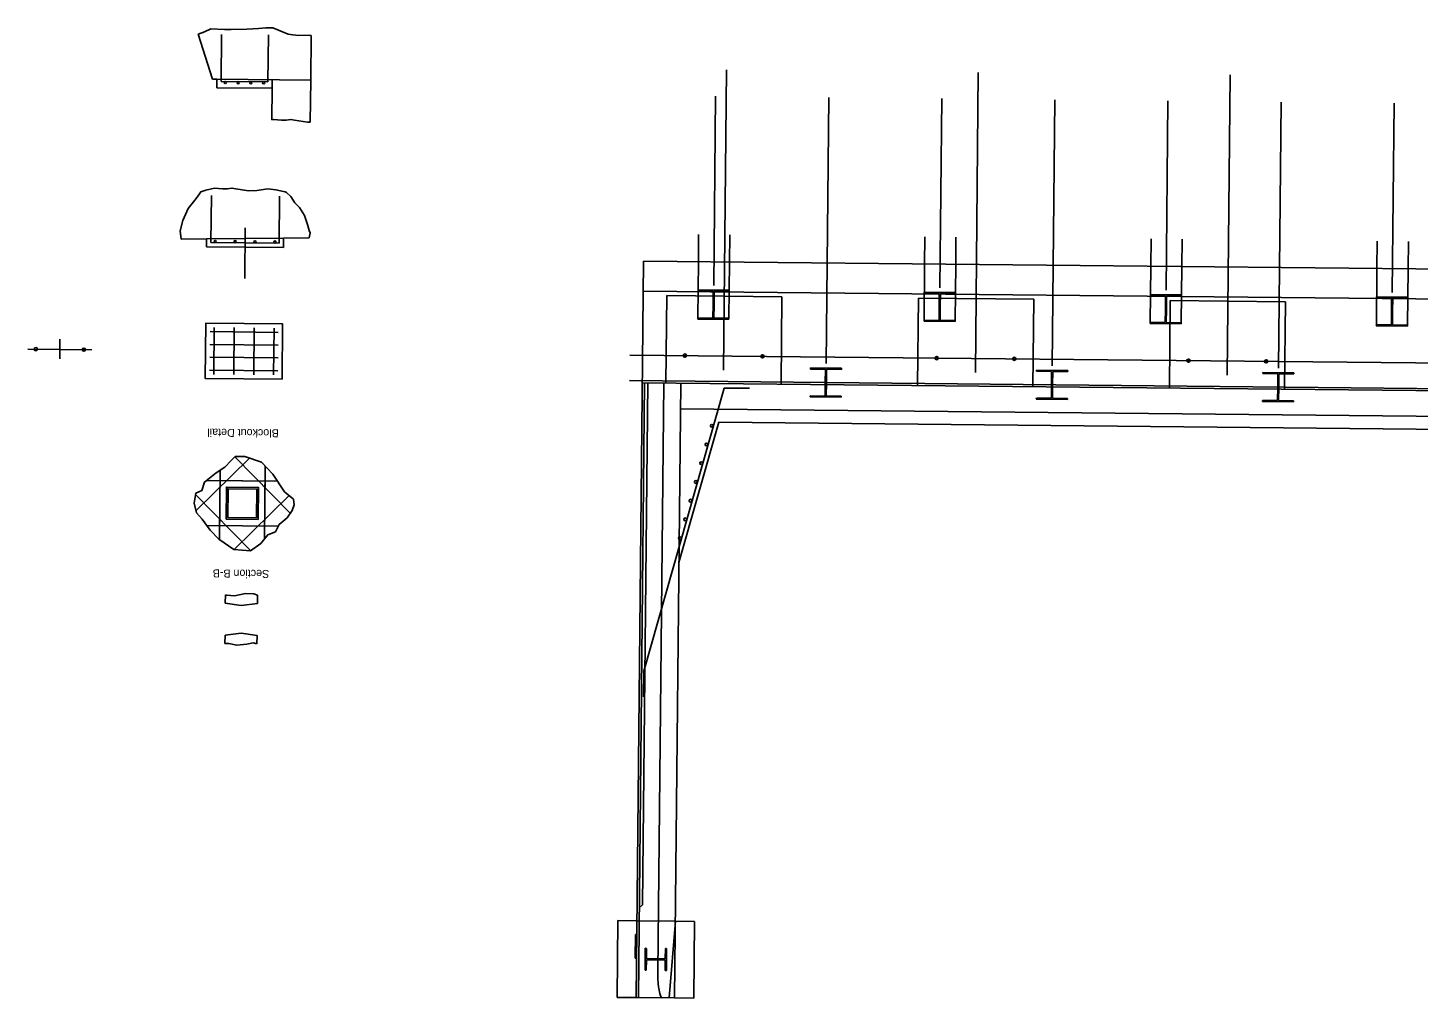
# Model space of a CAD drawing. Extents: x 632022 to 632319, y 373181 to 373252.
# Drawn here: x 632208.9 to 632263.2, y 373182 to 373219.8 of the extents above; entities that cross this region are included whole.
import ezdxf

# ---------------------------------------------------------------- set-up
doc = ezdxf.new("R2010")
doc.units = 0
for name, color, linetype in [('B_Boring', 7, 'Continuous'), ('B_Boring Annot', 7, 'Continuous'), ('BD-LEGEND', 7, 'Continuous'), ('BD-PROP-COSS', 7, 'Continuous'), ('BD-REMOVE', 7, 'Continuous'), ('R_Anno_Text', 7, 'Continuous'), ('R_Border_Scale', 7, 'Continuous'), ('R_Proposed Const Limits Cut', 7, 'Continuous'), ('R_Proposed Const Limits Fill', 7, 'Continuous'), ('R_Road Edge of Travel', 7, 'Continuous'), ('R_Shade Removal', 7, 'Continuous'), ('R_Wall', 7, 'Continuous')]:
    doc.layers.add(name, color=color, linetype=linetype)

msp = doc.modelspace()

# ---------------------------------------------------------------- linework, layer by layer
at = {"layer": 'B_Boring'}
for p, q in [((632233.142, 373205.975), (632232.94, 373185.601)), ((632232.814, 373185.477), (632232.94, 373185.601)), ((632234.225, 373184.963), (632232.725, 373184.978))]:
    msp.add_line(p, q, dxfattribs=at)
at = {"layer": 'B_Boring Annot'}
for p, q in [((632208.934, 373207.299), (632211.434, 373207.274)), ((632232.445, 373207.065), (632318.441, 373206.21))]:
    msp.add_line(p, q, dxfattribs=at)
at = {"layer": 'BD-LEGEND'}
for p, q in [((632216.148, 373217.835), (632215.582, 373219.591)), ((632219.999, 373219.547), (632219.981, 373217.797)), ((632216.148, 373217.835), (632216.315, 373217.834)), ((632219.981, 373217.797), (632219.965, 373216.163)), ((632218.466, 373216.251), (632218.478, 373217.479))]:
    msp.add_line(p, q, dxfattribs=at)
at = {"layer": 'BD-PROP-COSS'}
for p, q in [((632216.48, 373217.749), (632216.499, 373219.582)), ((632218.314, 373217.731), (632218.332, 373219.564)), ((632216.48, 373217.749), (632218.314, 373217.731)), ((632216.085, 373211.46), (632216.103, 373213.294)), ((632218.751, 373211.434), (632218.769, 373213.267)), ((632218.751, 373211.434), (632216.085, 373211.46)), ((632216.05, 373207.978), (632218.717, 373207.951)), ((632216.2, 373206.31), (632216.218, 373208.143)), ((632216.978, 373206.302), (632216.996, 373208.135)), ((632217.774, 373208.128), (632217.756, 373206.294)), ((632218.552, 373208.12), (632218.533, 373206.287)), ((632218.712, 373207.451), (632216.045, 373207.478)), ((632218.707, 373206.951), (632216.04, 373206.978)), ((632218.702, 373206.452), (632216.035, 373206.478)), ((632232.99, 373194.726), (632236.123, 373205.778)), ((632236.123, 373205.778), (632237.123, 373205.768)), ((632217.021, 373203.091), (632219.181, 373200.887)), ((632215.503, 373200.991), (632217.592, 373203.039)), ((632216.45, 373202.572), (632216.423, 373199.855)), ((632218.201, 373202.737), (632218.173, 373199.883)), ((632215.904, 373202.165), (632218.687, 373202.138)), ((632218.57, 373202.139), (632216.07, 373202.164)), ((632216.424, 373200.035), (632216.449, 373202.535)), ((632218.174, 373200.018), (632218.199, 373202.518)), ((632215.489, 373201.618), (632217.633, 373199.431)), ((632216.99, 373199.473), (632219.138, 373201.579)), ((632218.72, 373200.387), (632215.916, 373200.415)), ((632232.99, 373194.726), (632232.98, 373193.726))]:
    msp.add_line(p, q, dxfattribs=at)
for centre, radius in [((632216.647, 373217.705), 0.0417), ((632217.147, 373217.7), 0.0417), ((632217.647, 373217.695), 0.0417), ((632218.147, 373217.691), 0.0417), ((632216.252, 373211.5), 0.0417), ((632217.029, 373211.493), 0.0417), ((632217.807, 373211.485), 0.0417), ((632218.585, 373211.477), 0.0417), ((632235.646, 373204.304), 0.0556), ((632235.439, 373203.573), 0.0556), ((632235.232, 373202.842), 0.0556), ((632235.025, 373202.111), 0.0556), ((632234.818, 373201.379), 0.0556), ((632234.611, 373200.648), 0.0556), ((632234.404, 373199.917), 0.0556)]:
    msp.add_circle(centre, radius, dxfattribs=at)
at = {"layer": 'R_Anno_Text'}
for centre in [(632209.246, 373207.296), (632211.121, 373207.277), (632234.596, 373207.044), (632237.627, 373207.013), (632244.429, 373206.946), (632247.46, 373206.916), (632254.262, 373206.848), (632257.293, 373206.818)]:
    msp.add_circle(centre, 0.0625, dxfattribs=at)
at = {"layer": 'R_Border_Scale'}
for p, q in [((632219.981, 373217.797), (632216.315, 373217.834)), ((632218.478, 373217.479), (632218.481, 373217.812)), ((632218.92, 373211.629), (632215.919, 373211.599))]:
    msp.add_line(p, q, dxfattribs=at)
at = {"layer": 'R_Proposed Const Limits Cut'}
msp.add_lwpolyline([(632232.711, 373183.519), (632232.659, 373183.52), (632232.668, 373184.437), (632232.72, 373184.436)], close=True, dxfattribs=at)
at = {"layer": 'R_Proposed Const Limits Fill'}
for p, q in [((632236.222, 373218.196), (632236.106, 373206.479)), ((632246.055, 373218.098), (632245.939, 373206.381)), ((632255.888, 373218), (632255.772, 373206.283)), ((632217.424, 373212.034), (632217.404, 373210.054)), ((632210.188, 373207.69), (632210.18, 373206.912))]:
    msp.add_line(p, q, dxfattribs=at)
at = {"layer": 'R_Road Edge of Travel'}
for p, q in [((632235.123, 373210.705), (632235.133, 373211.773)), ((632236.339, 373210.693), (632236.35, 373211.761)), ((632243.956, 373210.617), (632243.966, 373211.685)), ((632245.172, 373210.605), (632245.183, 373211.673)), ((632252.789, 373210.53), (632252.799, 373211.597)), ((632254.005, 373210.517), (632254.016, 373211.585)), ((632261.622, 373210.442), (632261.632, 373211.51)), ((632262.838, 373210.43), (632262.849, 373211.498)), ((632235.101, 373208.514), (632235.123, 373210.705)), ((632236.318, 373208.502), (632236.339, 373210.693)), ((632243.934, 373208.426), (632243.956, 373210.617)), ((632245.151, 373208.414), (632245.172, 373210.605)), ((632252.767, 373208.338), (632252.789, 373210.53)), ((632253.983, 373208.326), (632254.005, 373210.517)), ((632261.6, 373208.251), (632261.622, 373210.442)), ((632262.816, 373208.238), (632262.838, 373210.43)), ((632235.112, 373209.605), (632236.329, 373209.593)), ((632235.112, 373209.563), (632235.112, 373209.605)), ((632235.112, 373209.605), (632236.329, 373209.593)), ((632235.112, 373209.563), (632235.112, 373209.605)), ((632235.112, 373209.563), (632235.699, 373209.557)), ((632235.112, 373209.563), (632235.699, 373209.557)), ((632235.699, 373209.557), (632235.694, 373209.033)), ((632235.699, 373209.557), (632235.694, 373209.033)), ((632235.741, 373209.557), (632235.736, 373209.032)), ((632235.741, 373209.557), (632235.736, 373209.032)), ((632236.328, 373209.551), (632235.741, 373209.557)), ((632236.328, 373209.551), (632235.741, 373209.557)), ((632236.328, 373209.551), (632236.329, 373209.593)), ((632236.328, 373209.551), (632236.329, 373209.593)), ((632243.944, 373209.475), (632243.945, 373209.517)), ((632243.944, 373209.475), (632244.532, 373209.469)), ((632243.945, 373209.517), (632245.161, 373209.505)), ((632244.532, 373209.469), (632244.526, 373208.945)), ((632244.574, 373209.469), (632244.569, 373208.944)), ((632245.161, 373209.463), (632244.574, 373209.469)), ((632245.161, 373209.463), (632245.161, 373209.505)), ((632252.777, 373209.387), (632252.778, 373209.43)), ((632252.777, 373209.387), (632253.365, 373209.382)), ((632252.778, 373209.43), (632253.994, 373209.417)), ((632253.365, 373209.382), (632253.359, 373208.857)), ((632253.407, 373209.381), (632253.401, 373208.857)), ((632253.994, 373209.375), (632253.407, 373209.381)), ((632253.994, 373209.375), (632253.994, 373209.417)), ((632261.61, 373209.3), (632261.611, 373209.342)), ((632261.61, 373209.3), (632262.197, 373209.294)), ((632261.611, 373209.342), (632262.827, 373209.33)), ((632262.197, 373209.294), (632262.192, 373208.769)), ((632262.24, 373209.293), (632262.234, 373208.769)), ((632262.827, 373209.288), (632262.24, 373209.293)), ((632262.827, 373209.288), (632262.827, 373209.33)), ((632235.101, 373208.514), (632235.101, 373208.472)), ((632235.101, 373208.514), (632235.688, 373208.508)), ((632235.101, 373208.514), (632235.101, 373208.472)), ((632235.101, 373208.514), (632235.688, 373208.508)), ((632235.688, 373208.508), (632235.694, 373209.033)), ((632235.688, 373208.508), (632235.694, 373209.033)), ((632235.736, 373209.032), (632235.694, 373209.033)), ((632235.736, 373209.032), (632235.694, 373209.033)), ((632235.73, 373208.508), (632235.736, 373209.032)), ((632235.73, 373208.508), (632235.736, 373209.032)), ((632244.521, 373208.42), (632244.526, 373208.945)), ((632244.569, 373208.944), (632244.526, 373208.945)), ((632244.563, 373208.42), (632244.569, 373208.944)), ((632253.354, 373208.333), (632253.359, 373208.857)), ((632253.401, 373208.857), (632253.359, 373208.857)), ((632253.396, 373208.332), (632253.401, 373208.857)), ((632262.187, 373208.245), (632262.192, 373208.769)), ((632262.234, 373208.769), (632262.192, 373208.769)), ((632262.229, 373208.244), (632262.234, 373208.769)), ((632235.101, 373208.472), (632236.317, 373208.46)), ((632235.101, 373208.472), (632236.317, 373208.46)), ((632236.318, 373208.502), (632235.73, 373208.508)), ((632236.318, 373208.502), (632235.73, 373208.508)), ((632236.318, 373208.502), (632236.317, 373208.46)), ((632236.318, 373208.502), (632236.317, 373208.46)), ((632243.934, 373208.426), (632243.934, 373208.384)), ((632243.934, 373208.426), (632244.521, 373208.42)), ((632243.934, 373208.384), (632245.15, 373208.372)), ((632245.151, 373208.414), (632244.563, 373208.42)), ((632245.151, 373208.414), (632245.15, 373208.372)), ((632252.767, 373208.338), (632252.766, 373208.296)), ((632252.766, 373208.296), (632253.983, 373208.284)), ((632252.767, 373208.338), (632253.354, 373208.333)), ((632253.983, 373208.326), (632253.396, 373208.332)), ((632253.983, 373208.326), (632253.983, 373208.284)), ((632261.6, 373208.251), (632261.599, 373208.208)), ((632261.599, 373208.208), (632262.816, 373208.196)), ((632261.6, 373208.251), (632262.187, 373208.245)), ((632262.816, 373208.238), (632262.229, 373208.244)), ((632262.816, 373208.238), (632262.816, 373208.196)), ((632239.498, 373206.519), (632239.499, 373206.561)), ((632239.498, 373206.519), (632239.499, 373206.561)), ((632239.498, 373206.519), (632240.085, 373206.514)), ((632239.498, 373206.519), (632240.086, 373206.514)), ((632239.499, 373206.561), (632240.715, 373206.549)), ((632239.499, 373206.561), (632240.715, 373206.549)), ((632240.085, 373206.514), (632240.08, 373205.989)), ((632240.086, 373206.514), (632240.08, 373205.989)), ((632240.127, 373206.513), (632240.122, 373205.989)), ((632240.128, 373206.513), (632240.122, 373205.989)), ((632240.715, 373206.507), (632240.127, 373206.513)), ((632240.715, 373206.507), (632240.128, 373206.513)), ((632240.715, 373206.507), (632240.715, 373206.549)), ((632240.715, 373206.507), (632240.715, 373206.549)), ((632248.331, 373206.432), (632248.332, 373206.474)), ((632248.331, 373206.432), (632248.918, 373206.426)), ((632248.332, 373206.474), (632249.548, 373206.462)), ((632248.918, 373206.426), (632248.913, 373205.901)), ((632248.961, 373206.425), (632248.955, 373205.901)), ((632249.548, 373206.419), (632248.961, 373206.425)), ((632249.548, 373206.419), (632249.548, 373206.462)), ((632257.164, 373206.386), (632258.381, 373206.374)), ((632257.164, 373206.344), (632257.164, 373206.386)), ((632257.164, 373206.344), (632257.751, 373206.338)), ((632257.751, 373206.338), (632257.746, 373205.813)), ((632257.793, 373206.337), (632257.788, 373205.813)), ((632258.381, 373206.332), (632257.793, 373206.337)), ((632258.381, 373206.332), (632258.381, 373206.374)), ((632240.075, 373205.464), (632240.08, 373205.989)), ((632240.075, 373205.464), (632240.08, 373205.989)), ((632240.122, 373205.989), (632240.08, 373205.989)), ((632240.122, 373205.989), (632240.08, 373205.989)), ((632240.117, 373205.464), (632240.122, 373205.989)), ((632240.117, 373205.464), (632240.122, 373205.989)), ((632248.908, 373205.377), (632248.913, 373205.901)), ((632248.955, 373205.901), (632248.913, 373205.901)), ((632248.95, 373205.376), (632248.955, 373205.901)), ((632257.741, 373205.289), (632257.746, 373205.813)), ((632257.788, 373205.813), (632257.746, 373205.813)), ((632257.783, 373205.288), (632257.788, 373205.813)), ((632239.488, 373205.47), (632239.487, 373205.428)), ((632239.488, 373205.47), (632239.487, 373205.428)), ((632239.487, 373205.428), (632240.704, 373205.416)), ((632239.487, 373205.428), (632240.704, 373205.416)), ((632239.488, 373205.47), (632240.075, 373205.464)), ((632239.488, 373205.47), (632240.075, 373205.464)), ((632240.704, 373205.458), (632240.117, 373205.464)), ((632240.704, 373205.458), (632240.117, 373205.464)), ((632240.704, 373205.458), (632240.704, 373205.416)), ((632240.704, 373205.458), (632240.704, 373205.416)), ((632248.321, 373205.382), (632248.32, 373205.34)), ((632248.32, 373205.34), (632249.537, 373205.328)), ((632248.321, 373205.382), (632248.908, 373205.377)), ((632249.537, 373205.37), (632248.95, 373205.376)), ((632249.537, 373205.37), (632249.537, 373205.328)), ((632257.154, 373205.295), (632257.153, 373205.253)), ((632257.153, 373205.253), (632258.37, 373205.24)), ((632257.154, 373205.295), (632257.741, 373205.289)), ((632258.37, 373205.283), (632257.783, 373205.288)), ((632258.37, 373205.283), (632258.37, 373205.24)), ((632233.048, 373183.902), (632233.039, 373183.047)), ((632233.095, 373183.901), (632233.048, 373183.902)), ((632233.091, 373183.497), (632233.095, 373183.901)), ((632233.83, 373183.49), (632233.834, 373183.894)), ((632233.834, 373183.894), (632233.881, 373183.893)), ((632233.881, 373183.893), (632233.873, 373183.039)), ((632233.086, 373183.047), (632233.039, 373183.047)), ((632233.086, 373183.047), (632233.09, 373183.451)), ((632233.09, 373183.451), (632233.46, 373183.447)), ((632233.091, 373183.497), (632233.461, 373183.494)), ((632233.46, 373183.447), (632233.461, 373183.494)), ((632233.83, 373183.443), (632233.46, 373183.447)), ((632233.83, 373183.49), (632233.461, 373183.494)), ((632233.826, 373183.04), (632233.83, 373183.443)), ((632233.826, 373183.04), (632233.873, 373183.039))]:
    msp.add_line(p, q, dxfattribs=at)
at = {"layer": 'R_Shade Removal'}
for p, q in [((632216.311, 373217.5), (632216.315, 373217.834)), ((632218.478, 373217.479), (632216.311, 373217.5)), ((632214.919, 373211.589), (632215.919, 373211.599)), ((632215.916, 373211.295), (632215.919, 373211.599)), ((632218.916, 373211.266), (632215.916, 373211.295)), ((632218.916, 373211.266), (632218.92, 373211.629)), ((632218.92, 373211.629), (632219.92, 373211.639)), ((632232.981, 373210.726), (632232.695, 373181.978)), ((632232.981, 373210.726), (632317.977, 373209.881)), ((632232.97, 373209.56), (632317.966, 373208.715)), ((632233.885, 373209.384), (632233.851, 373205.968)), ((632238.384, 373209.339), (632233.885, 373209.384)), ((632238.384, 373209.339), (632238.35, 373205.923)), ((632243.718, 373209.286), (632243.684, 373205.87)), ((632248.217, 373209.242), (632243.718, 373209.286)), ((632248.217, 373209.242), (632248.183, 373205.825)), ((632253.55, 373209.189), (632253.516, 373205.772)), ((632258.05, 373209.144), (632253.55, 373209.189)), ((632258.05, 373209.144), (632258.016, 373205.727)), ((632233.017, 373205.976), (632232.779, 373181.977)), ((632232.934, 373205.977), (632317.93, 373205.132)), ((632233.539, 373182.97), (632233.767, 373205.968)), ((632234.434, 373205.962), (632234.195, 373181.963)), ((632234.424, 373204.962), (632316.42, 373204.147)), ((632235.919, 373204.447), (632234.364, 373198.962)), ((632235.919, 373204.447), (632314.915, 373203.662)), ((632216.651, 373197.705), (632216.648, 373197.38)), ((632217.901, 373197.693), (632217.898, 373197.368)), ((632216.636, 373196.13), (632216.632, 373195.805)), ((632217.885, 373196.118), (632217.882, 373195.793)), ((632231.975, 373184.985), (632231.946, 373181.985)), ((632231.975, 373184.985), (632232.725, 373184.978)), ((632234.225, 373184.963), (632233.987, 373181.965)), ((632234.225, 373184.963), (632234.975, 373184.955)), ((632234.975, 373184.955), (632234.945, 373181.955)), ((632231.946, 373181.985), (632232.695, 373181.978)), ((632232.695, 373181.978), (632234.195, 373181.963)), ((632232.695, 373181.978), (632234.195, 373181.963)), ((632234.195, 373181.963), (632234.945, 373181.955))]:
    msp.add_line(p, q, dxfattribs=at)
for points in [[(632215.582, 373219.591), (632215.835, 373219.683), (632216.083, 373219.803), (632216.61, 373219.781), (632216.873, 373219.778), (632217.488, 373219.789), (632217.726, 373219.805), (632217.945, 373219.82), (632218.227, 373219.835), (632218.508, 373219.841), (632218.508, 373219.841), (632219.103, 373219.589), (632219.287, 373219.569), (632219.515, 373219.541), (632219.884, 373219.555), (632219.999, 373219.547)], [(632219.965, 373216.163), (632219.851, 373216.16), (632219.354, 373216.241), (632219.209, 373216.267), (632219.023, 373216.234), (632218.837, 373216.241), (632218.526, 373216.264), (632218.466, 373216.251)], [(632219.92, 373211.639), (632219.963, 373211.831), (632219.923, 373211.931), (632219.923, 373211.931), (632219.856, 373212.168), (632219.738, 373212.516), (632219.551, 373212.824), (632219.362, 373213.002), (632219.204, 373213.249), (632219.039, 373213.407), (632218.985, 373213.437), (632218.919, 373213.453), (632218.624, 373213.521), (632218.308, 373213.55), (632217.876, 373213.484), (632217.549, 373213.477), (632217.053, 373213.557), (632216.908, 373213.584), (632216.722, 373213.55), (632216.536, 373213.557), (632216.225, 373213.58), (632215.883, 373213.508), (632215.686, 373213.44), (632215.635, 373213.36), (632215.503, 373213.171), (632215.203, 373212.787), (632214.982, 373212.312), (632214.883, 373211.911), (632214.919, 373211.589)], [(632217.898, 373197.368), (632217.272, 373197.291), (632216.648, 373197.38)], [(632217.885, 373196.118), (632217.261, 373196.207), (632216.636, 373196.13)]]:
    msp.add_lwpolyline(points, dxfattribs=at)
for points in [[(632218.865, 373206.117), (632215.865, 373206.146), (632215.887, 373208.313), (632218.887, 373208.283)], [(632217.93, 373200.645), (632216.681, 373200.658), (632216.693, 373201.908), (632217.943, 373201.895)], [(632217.869, 373200.708), (632216.744, 373200.719), (632216.755, 373201.844), (632217.88, 373201.833)]]:
    msp.add_lwpolyline(points, close=True, dxfattribs=at)
msp.add_ellipse((632233.724, 373182.968), major_axis=(-0.01, -1), ratio=0.1848, start_param=4.712389, end_param=6.283186, dxfattribs=at)
at = {"layer": 'R_Wall'}
for p, q in [((632235.795, 373217.166), (632235.722, 373209.776)), ((632240.212, 373217.121), (632240.109, 373206.732)), ((632244.628, 373217.078), (632244.555, 373209.688)), ((632249.045, 373217.031), (632248.942, 373206.644)), ((632253.461, 373216.99), (632253.388, 373209.6)), ((632257.878, 373216.942), (632257.775, 373206.557)), ((632262.294, 373216.902), (632262.221, 373209.513)), ((632232.435, 373206.065), (632318.431, 373205.21))]:
    msp.add_line(p, q, dxfattribs=at)
for points in [[(632215.437, 373201.283), (632215.524, 373200.902), (632215.742, 373200.655), (632215.742, 373200.655), (632216.055, 373200.223), (632216.398, 373199.872), (632216.974, 373199.474), (632217.627, 373199.427), (632218.038, 373199.712), (632218.305, 373200.049), (632218.605, 373200.164), (632218.753, 373200.453), (632219.06, 373200.704), (632219.258, 373201.002), (632219.337, 373201.218), (632219.31, 373201.435), (632218.957, 373201.73), (632218.505, 373202.411), (632218.061, 373202.888), (632217.405, 373203.099), (632217.033, 373203.102), (632216.873, 373202.95), (632216.63, 373202.689), (632216.292, 373202.47), (632216.096, 373202.315), (632215.831, 373202.108), (632215.731, 373201.779), (632215.497, 373201.674), (632215.437, 373201.283)], [(632217.901, 373197.693), (632217.755, 373197.746), (632217.437, 373197.755), (632217.004, 373197.666), (632216.69, 373197.696), (632216.651, 373197.705)], [(632216.632, 373195.805), (632216.783, 373195.8), (632217.096, 373195.743), (632217.488, 373195.783), (632217.731, 373195.827), (632217.882, 373195.793)]]:
    msp.add_lwpolyline(points, dxfattribs=at)

# ---------------------------------------------------------------- texts
at = {"layer": 'BD-REMOVE'}
for s, p in [('Blockout Detail', (632218.735, 373204.165)), ('Section B-B', (632218.362, 373198.674))]:
    msp.add_text(s, height=0.3125, rotation=179.4304, dxfattribs=at).set_placement(p)

doc.saveas('drawing.dxf')
